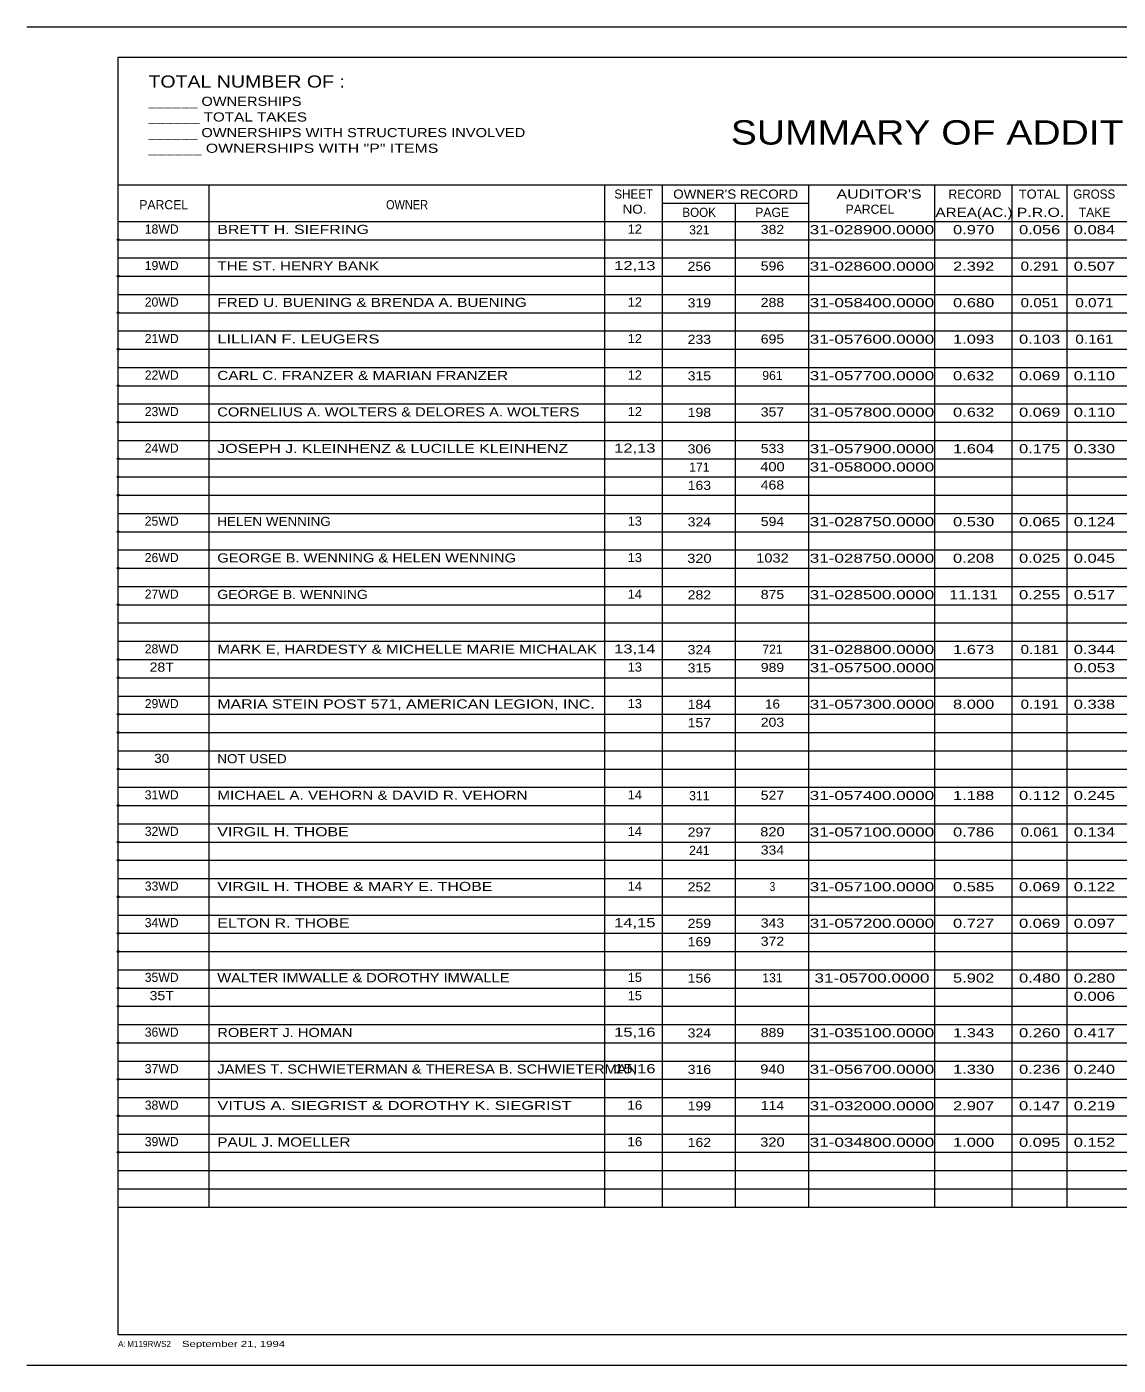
# Model space of a CAD drawing. Extents: x -1 to 34.5, y 0 to 22.
# Drawn here: x -1 to 16.94, y 0 to 22 of the extents above; entities that cross this region are included whole.
import ezdxf
from ezdxf.enums import TextEntityAlignment as Align

# ---------------------------------------------------------------- set-up
doc = ezdxf.new("R2010")
doc.units = 0
doc.header["$LTSCALE"] = 0.06
doc.header["$PDMODE"] = 32
doc.header["$PDSIZE"] = 0.03
doc.layers.add('1', color=7, linetype='Continuous', lineweight=13)

msp = doc.modelspace()

# ---------------------------------------------------------------- linework, layer by layer
at = {"layer": '1'}
for p, q in [((-1, 22), (34.5, 22)), ((0.5, 21.5), (34, 21.5)), ((0.5, 0.5), (0.5, 21.5)), ((0.5, 19.4), (34, 19.4)), ((2, 2.6), (2, 19.4)), ((8.5, 2.6), (8.5, 19.4)), ((9.45025, 2.6), (9.45025, 19.4)), ((11.85025, 2.6), (11.85025, 19.4)), ((13.92625, 2.6), (13.92625, 19.4)), ((15.19617, 2.6), (15.19617, 19.4)), ((16.09617, 2.6), (16.09617, 19.4)), ((9.45025, 19.1), (11.85025, 19.1)), ((10.65025, 2.6), (10.65025, 19.1)), ((0.5, 18.8), (34, 18.8)), ((0.5, 18.5), (34, 18.5)), ((0.5, 18.2), (34, 18.2)), ((0.5, 17.9), (34, 17.9)), ((0.5, 17.6), (34, 17.6)), ((0.5, 17.3), (34, 17.3)), ((0.5, 17), (34, 17)), ((0.5, 16.7), (34, 16.7)), ((0.5, 16.4), (34, 16.4)), ((0.5, 16.1), (34, 16.1)), ((0.5, 15.8), (34, 15.8)), ((0.5, 15.5), (34, 15.5)), ((0.5, 15.2), (34, 15.2)), ((0.5, 14.9), (34, 14.9)), ((0.5, 14.6), (34, 14.6)), ((0.5, 14.3), (34, 14.3)), ((0.5, 14), (34, 14)), ((0.5, 13.7), (34, 13.7)), ((0.5, 13.4), (34, 13.4)), ((0.5, 13.1), (34, 13.1)), ((0.5, 12.8), (34, 12.8)), ((0.5, 12.5), (34, 12.5)), ((0.5, 12.2), (34, 12.2)), ((0.5, 11.9), (34, 11.9)), ((0.5, 11.6), (34, 11.6)), ((0.5, 11.3), (34, 11.3)), ((0.5, 11), (34, 11)), ((0.5, 10.7), (34, 10.7)), ((0.5, 10.4), (34, 10.4)), ((0.5, 10.1), (34, 10.1)), ((0.5, 9.8), (34, 9.8)), ((0.5, 9.5), (34, 9.5)), ((0.5, 9.2), (34, 9.2)), ((0.5, 8.9), (34, 8.9)), ((0.5, 8.6), (34, 8.6)), ((0.5, 8.3), (34, 8.3)), ((0.5, 8), (34, 8)), ((0.5, 7.7), (34, 7.7)), ((0.5, 7.4), (34, 7.4)), ((0.5, 7.1), (34, 7.1)), ((0.5, 6.8), (34, 6.8)), ((0.5, 6.5), (34, 6.5)), ((0.5, 6.2), (34, 6.2)), ((0.5, 5.9), (34, 5.9)), ((0.5, 5.6), (34, 5.6)), ((0.5, 5.3), (34, 5.3)), ((0.5, 5), (34, 5)), ((0.5, 4.7), (34, 4.7)), ((0.5, 4.4), (34, 4.4)), ((0.5, 4.1), (34, 4.1)), ((0.5, 3.8), (34, 3.8)), ((0.5, 3.5), (34, 3.5)), ((0.5, 3.2), (34, 3.2)), ((0.5, 2.9), (34, 2.9)), ((0.5, 2.6), (34, 2.6)), ((-1, 0), (34.5, 0))]:
    msp.add_line(p, q, dxfattribs=at)
msp.add_lwpolyline([(34, 21.5), (34, 0.5), (0.5, 0.5)], dxfattribs=at)
for p in [(0.5, 18.5), (0.5, 17.9), (0.5, 17.3), (0.5, 16.7), (0.5, 16.1), (0.5, 15.5), (0.5, 14.9), (0.5, 14.6), (0.5, 14.3), (0.5, 13.7), (0.5, 13.1), (0.5, 12.5), (0.5, 11.6), (0.5, 11.3), (0.5, 10.7), (0.5, 10.4), (0.5, 9.8), (0.5, 9.2), (0.5, 8.6), (0.5, 8.3), (0.5, 7.7), (0.5, 7.1), (0.5, 6.8), (0.5, 6.2), (0.5, 5.9), (0.5, 5.3), (0.5, 4.7), (0.5, 4.1), (0.5, 3.5)]:
    msp.add_point(p, dxfattribs=at)

# ---------------------------------------------------------------- texts
for s, height, width, p in [('TOTAL NUMBER OF :', 0.2, 1.2, (1, 21)), ('______ OWNERSHIPS', 0.15, 1.2, (1, 20.7)), ('______ TOTAL TAKES', 0.15, 1.25, (1, 20.44283)), ('______ OWNERSHIPS WITH STRUCTURES INVOLVED', 0.15, 1.2, (1, 20.18575)), ('______ OWNERSHIPS WITH "P" ITEMS', 0.15, 1.3, (1, 19.92858)), ("AUDITOR'S ", 0.15, 1.3, (12.30883, 19.176)), (' NO.', 0.15, 1.1, (8.73083, 18.92683)), ('BRETT H. SIEFRING', 0.15, 1.3, (2.13167, 18.59433)), ('THE ST. HENRY BANK', 0.15, 1.25, (2.13167, 17.99433)), ('FRED U. BUENING & BRENDA A. BUENING', 0.15, 1.25, (2.13167, 17.39433)), ('LILLIAN F. LEUGERS', 0.15, 1.35, (2.13167, 16.79433)), ('CARL C. FRANZER & MARIAN FRANZER', 0.15, 1.25, (2.13167, 16.19433)), ('CORNELIUS A. WOLTERS & DELORES A. WOLTERS', 0.15, 1.2, (2.13167, 15.59433)), ('JOSEPH J. KLEINHENZ & LUCILLE KLEINHENZ', 0.15, 1.3, (2.13167, 14.99433)), ('HELEN WENNING', 0.15, 1.1, (2.13167, 13.79433)), ('GEORGE B. WENNING & HELEN WENNING', 0.15, 1.2, (2.13167, 13.19433)), ('GEORGE B. WENNING', 0.15, 1.15, (2.13167, 12.59433)), ('MARK E, HARDESTY & MICHELLE MARIE MICHALAK', 0.15, 1.25, (2.13167, 11.69433)), ('MARIA STEIN POST 571, AMERICAN LEGION, INC.', 0.15, 1.3, (2.13167, 10.79433)), ('NOT USED', 0.15, 1.1, (2.13167, 9.89433)), ('MICHAEL A. VEHORN & DAVID R. VEHORN', 0.15, 1.25, (2.13167, 9.29433)), ('VIRGIL H. THOBE', 0.15, 1.3, (2.13167, 8.69433)), ('VIRGIL H. THOBE & MARY E. THOBE', 0.15, 1.3, (2.13167, 7.79433)), ('ELTON R. THOBE ', 0.15, 1.3, (2.13167, 7.19433)), ('WALTER IMWALLE & DOROTHY IMWALLE', 0.15, 1.2, (2.13167, 6.29433)), ('ROBERT J. HOMAN', 0.15, 1.2, (2.13167, 5.39433)), ('JAMES T. SCHWIETERMAN & THERESA B. SCHWIETERMAN', 0.15, 1.2, (2.13167, 4.79433)), ('VITUS A. SIEGRIST & DOROTHY K. SIEGRIST', 0.15, 1.35, (2.13167, 4.19433)), ('PAUL J. MOELLER', 0.15, 1.25, (2.13167, 3.59433)), ('September 21, 1994', 0.1, 1.4, (1.55, 0.3))]:
    msp.add_text(s, height=height, dxfattribs=dict(at, width=width)).set_placement(p)
for s, height, width, p in [('SUMMARY OF ADDITIONAL RIGHT-OF-WAY', 0.4, 1.2, (17.2385, 20.06342)), ('OWNER', 0.15, 0.9, (5.25004, 19)), ('SHEET', 0.15, 0.95, (8.97467, 19.17683)), ("OWNER'S RECORD", 0.15, 1.1, (10.65025, 19.175)), ('TOTAL', 0.15, 1.05, (15.64387, 19.175)), ('GROSS', 0.15, 0.95, (16.54367, 19.175)), ('BOOK', 0.15, 0.95, (10.05029, 18.875)), ('AREA(AC.)', 0.15, 1.25, (14.56738, 18.875)), ('P.R.O.', 0.15, 1.3, (15.66092, 18.875)), ('12', 0.15, 1.05, (8.9935, 18.60025)), ('382', 0.15, 1.15, (11.25512, 18.59383)), ('31-028900.0000', 0.15, 1.4, (12.89025, 18.59)), ('0.970', 0.15, 1.35, (14.56129, 18.59)), ('0.056', 0.15, 1.35, (15.64621, 18.59)), ('0.084', 0.15, 1.35, (16.54612, 18.59)), ('12,13', 0.15, 1.35, (8.99346, 18.00025)), ('256', 0.15, 1.15, (10.05387, 17.9875)), ('596', 0.15, 1.15, (11.25521, 17.99383)), ('31-028600.0000', 0.15, 1.4, (12.89025, 17.99)), ('2.392', 0.15, 1.35, (14.56121, 17.99)), ('0.291', 0.15, 1.25, (15.64617, 17.99)), ('0.507', 0.15, 1.35, (16.54612, 17.99)), ('12', 0.15, 1.05, (8.9935, 17.40025)), ('319', 0.15, 1.15, (10.05379, 17.3875)), ('288', 0.15, 1.15, (11.25512, 17.39383)), ('31-058400.0000', 0.15, 1.4, (12.89025, 17.39)), ('0.680', 0.15, 1.35, (14.56129, 17.39)), ('0.051', 0.15, 1.25, (15.64617, 17.39)), ('0.071', 0.15, 1.25, (16.54617, 17.39)), ('12', 0.15, 1.05, (8.9935, 16.80025)), ('695', 0.15, 1.15, (11.25512, 16.79383)), ('31-057600.0000', 0.15, 1.4, (12.89025, 16.79)), ('1.093', 0.15, 1.35, (14.56121, 16.79)), ('0.103', 0.15, 1.35, (15.64612, 16.79)), ('0.161', 0.15, 1.25, (16.54617, 16.79)), ('233', 0.15, 1.15, (10.05379, 16.7875)), ('12', 0.15, 1.05, (8.9935, 16.20025)), ('315', 0.15, 1.15, (10.05379, 16.1875)), ('31-057700.0000', 0.15, 1.4, (12.89025, 16.19)), ('0.632', 0.15, 1.35, (14.56121, 16.19)), ('0.069', 0.15, 1.35, (15.64612, 16.19)), ('0.110', 0.15, 1.35, (16.54621, 16.19)), ('12', 0.15, 1.05, (8.9935, 15.60025)), ('198', 0.15, 1.15, (10.05379, 15.5875)), ('357', 0.15, 1.15, (11.25512, 15.59383)), ('31-057800.0000', 0.15, 1.4, (12.89025, 15.59)), ('0.632', 0.15, 1.35, (14.56121, 15.59)), ('0.069', 0.15, 1.35, (15.64612, 15.59)), ('0.110', 0.15, 1.35, (16.54621, 15.59)), ('12,13', 0.15, 1.35, (8.99346, 15.00025)), ('306', 0.15, 1.15, (10.05387, 14.9875)), ('533', 0.15, 1.15, (11.25512, 14.99383)), ('31-057900.0000', 0.15, 1.4, (12.89025, 14.99)), ('1.604', 0.15, 1.35, (14.56121, 14.99)), ('0.175', 0.15, 1.35, (15.64612, 14.99)), ('0.330', 0.15, 1.35, (16.54621, 14.99)), ('400', 0.15, 1.2, (11.25521, 14.69383)), ('31-058000.0000', 0.15, 1.4, (12.89025, 14.69)), ('163', 0.15, 1.15, (10.05379, 14.3875)), ('468', 0.15, 1.15, (11.25512, 14.39383)), ('13', 0.15, 1.05, (8.9935, 13.80025)), ('324', 0.15, 1.15, (10.05379, 13.7875)), ('594', 0.15, 1.15, (11.25512, 13.79383)), ('31-028750.0000', 0.15, 1.4, (12.89025, 13.79)), ('0.530', 0.15, 1.35, (14.56129, 13.79)), ('0.065', 0.15, 1.35, (15.64612, 13.79)), ('0.124', 0.15, 1.35, (16.54612, 13.79)), ('13', 0.15, 1.05, (8.9935, 13.20025)), ('320', 0.15, 1.2, (10.05387, 13.1875)), ('1032', 0.15, 1.2, (11.25521, 13.19383)), ('31-028750.0000', 0.15, 1.4, (12.89025, 13.19)), ('0.208', 0.15, 1.35, (14.56121, 13.19)), ('0.025', 0.15, 1.35, (15.64612, 13.19)), ('0.045', 0.15, 1.35, (16.54612, 13.19)), ('14', 0.15, 1.05, (8.9935, 12.60025)), ('282', 0.15, 1.15, (10.05379, 12.5875)), ('875', 0.15, 1.15, (11.25512, 12.59383)), ('31-028500.0000', 0.15, 1.4, (12.89025, 12.59)), ('11.131', 0.15, 1.3, (14.56125, 12.59)), ('0.255', 0.15, 1.35, (15.64612, 12.59)), ('0.517', 0.15, 1.35, (16.54612, 12.59)), ('13,14', 0.15, 1.35, (8.99346, 11.70025)), ('324', 0.15, 1.15, (10.05379, 11.6875)), ('31-028800.0000', 0.15, 1.4, (12.89025, 11.69)), ('1.673', 0.15, 1.35, (14.56121, 11.69)), ('0.181', 0.15, 1.25, (15.64617, 11.69)), ('0.344', 0.15, 1.35, (16.54612, 11.69)), ('28T', 0.15, 1.15, (1.21771, 11.40025)), ('13', 0.15, 1.05, (8.9935, 11.40025)), ('315', 0.15, 1.15, (10.05379, 11.3875)), ('989', 0.15, 1.15, (11.25512, 11.39383)), ('31-057500.0000', 0.15, 1.4, (12.89025, 11.39)), ('0.053', 0.15, 1.35, (16.54612, 11.39)), ('13', 0.15, 1.05, (8.9935, 10.80025)), ('184', 0.15, 1.15, (10.05379, 10.7875)), ('16', 0.15, 1.1, (11.25517, 10.79383)), ('31-057300.0000', 0.15, 1.4, (12.89025, 10.79)), ('8.000', 0.15, 1.35, (14.56129, 10.79)), ('0.191', 0.15, 1.25, (15.64617, 10.79)), ('0.338', 0.15, 1.35, (16.54612, 10.79)), ('157', 0.15, 1.15, (10.05379, 10.4875)), ('203', 0.15, 1.15, (11.25512, 10.49383)), ('30', 0.15, 1.1, (1.21767, 9.90025)), ('14', 0.15, 1.05, (8.9935, 9.30025)), ('527', 0.15, 1.15, (11.25512, 9.29383)), ('31-057400.0000', 0.15, 1.4, (12.89025, 9.29)), ('1.188', 0.15, 1.35, (14.56121, 9.29)), ('0.112', 0.15, 1.35, (15.64612, 9.29)), ('0.245', 0.15, 1.35, (16.54612, 9.29)), ('14', 0.15, 1.05, (8.9935, 8.70025)), ('297', 0.15, 1.15, (10.05379, 8.6875)), ('820', 0.15, 1.2, (11.25521, 8.69383)), ('31-057100.0000', 0.15, 1.4, (12.89025, 8.69)), ('0.786', 0.15, 1.35, (14.56129, 8.69)), ('0.061', 0.15, 1.25, (15.64617, 8.69)), ('0.134', 0.15, 1.35, (16.54612, 8.69)), ('334', 0.15, 1.15, (11.25512, 8.39383)), ('14', 0.15, 1.05, (8.9935, 7.80025)), ('252', 0.15, 1.15, (10.05379, 7.7875)), ('3', 0.15, 0.8, (11.25517, 7.79383)), ('31-057100.0000', 0.15, 1.4, (12.89025, 7.79)), ('0.585', 0.15, 1.35, (14.56121, 7.79)), ('0.069', 0.15, 1.35, (15.64612, 7.79)), ('0.122', 0.15, 1.35, (16.54612, 7.79)), ('14,15', 0.15, 1.35, (8.99346, 7.20025)), ('259', 0.15, 1.15, (10.05379, 7.1875)), ('343', 0.15, 1.15, (11.25512, 7.19383)), ('31-057200.0000', 0.15, 1.4, (12.89025, 7.19)), ('0.727', 0.15, 1.35, (14.56121, 7.19)), ('0.069', 0.15, 1.35, (15.64612, 7.19)), ('0.097', 0.15, 1.35, (16.54612, 7.19)), ('372', 0.15, 1.15, (11.25512, 6.89383)), ('169', 0.15, 1.15, (10.05379, 6.8875)), ('15', 0.15, 1.05, (8.9935, 6.30025)), ('156', 0.15, 1.15, (10.05387, 6.2875)), ('31-05700.0000', 0.15, 1.4, (12.89025, 6.29)), ('5.902', 0.15, 1.35, (14.56121, 6.29)), ('0.480', 0.15, 1.35, (15.64621, 6.29)), ('0.280', 0.15, 1.35, (16.54621, 6.29)), ('35T', 0.15, 1.15, (1.21771, 6.00025)), ('15', 0.15, 1.05, (8.9935, 6.00025)), ('0.006', 0.15, 1.35, (16.54621, 5.99)), ('15,16', 0.15, 1.35, (8.99354, 5.40025)), ('324', 0.15, 1.15, (10.05379, 5.3875)), ('889', 0.15, 1.15, (11.25512, 5.39383)), ('31-035100.0000', 0.15, 1.4, (12.89025, 5.39)), ('1.343', 0.15, 1.35, (14.56121, 5.39)), ('0.260', 0.15, 1.35, (15.64621, 5.39)), ('0.417', 0.15, 1.35, (16.54612, 5.39)), ('15,16', 0.15, 1.35, (8.99354, 4.80025)), ('316', 0.15, 1.15, (10.05387, 4.7875)), ('940', 0.15, 1.2, (11.25521, 4.79383)), ('31-056700.0000', 0.15, 1.4, (12.89025, 4.79)), ('1.330', 0.15, 1.35, (14.56129, 4.79)), ('0.236', 0.15, 1.35, (15.64621, 4.79)), ('0.240', 0.15, 1.35, (16.54621, 4.79)), ('16', 0.15, 1.1, (8.9935, 4.20025)), ('199', 0.15, 1.15, (10.05379, 4.1875)), ('114', 0.15, 1.15, (11.25512, 4.19383)), ('31-032000.0000', 0.15, 1.4, (12.89025, 4.19)), ('2.907', 0.15, 1.35, (14.56121, 4.19)), ('0.147', 0.15, 1.35, (15.64612, 4.19)), ('0.219', 0.15, 1.35, (16.54612, 4.19)), ('16', 0.15, 1.1, (8.9935, 3.60025)), ('320', 0.15, 1.2, (11.25521, 3.59383)), ('31-034800.0000', 0.15, 1.4, (12.89025, 3.59)), ('1.000', 0.15, 1.35, (14.56129, 3.59)), ('0.095', 0.15, 1.35, (15.64612, 3.59)), ('0.152', 0.15, 1.35, (16.54612, 3.59)), ('162', 0.15, 1.15, (10.05379, 3.5875))]:
    msp.add_text(s, height=height, dxfattribs=dict(at, width=width)).set_placement(p, align=Align.CENTER)
for s, p in [('PARCEL', (1.25004, 19)), ('RECORD', (14.58121, 19.175)), ('PAGE', (11.25025, 18.875)), ('TAKE', (16.55008, 18.875)), ('18WD', (1.21762, 18.60025)), ('321', (10.05383, 18.5875)), ('19WD', (1.21762, 18.00025)), ('20WD', (1.21762, 17.40025)), ('21WD', (1.21762, 16.80025)), ('22WD', (1.21762, 16.20025)), ('961', (11.25517, 16.19383)), ('23WD', (1.21762, 15.60025)), ('24WD', (1.21762, 15.00025)), ('171', (10.05383, 14.6875)), ('25WD', (1.21762, 13.80025)), ('26WD', (1.21762, 13.20025)), ('27WD', (1.21762, 12.60025)), ('28WD', (1.21762, 11.70025)), ('721', (11.25517, 11.69383)), ('29WD', (1.21762, 10.80025)), ('31WD', (1.21762, 9.30025)), ('311', (10.05383, 9.2875)), ('32WD', (1.21762, 8.70025)), ('241', (10.05383, 8.3875)), ('33WD', (1.21762, 7.80025)), ('34WD', (1.21762, 7.20025)), ('35WD', (1.21762, 6.30025)), ('131', (11.25517, 6.29383)), ('36WD', (1.21762, 5.40025)), ('37WD', (1.21762, 4.80025)), ('38WD', (1.21762, 4.20025)), ('39WD', (1.21762, 3.60025))]:
    msp.add_text(s, height=0.15, dxfattribs=at).set_placement(p, align=Align.CENTER)
for s, height, p in [('PARCEL', 0.15, (12.45575, 18.926)), ('A:', 0.1, (0.5, 0.3)), ('M119RWS2', 0.1, (0.65, 0.3))]:
    msp.add_text(s, height=height, dxfattribs=at).set_placement(p)

doc.saveas('drawing.dxf')
